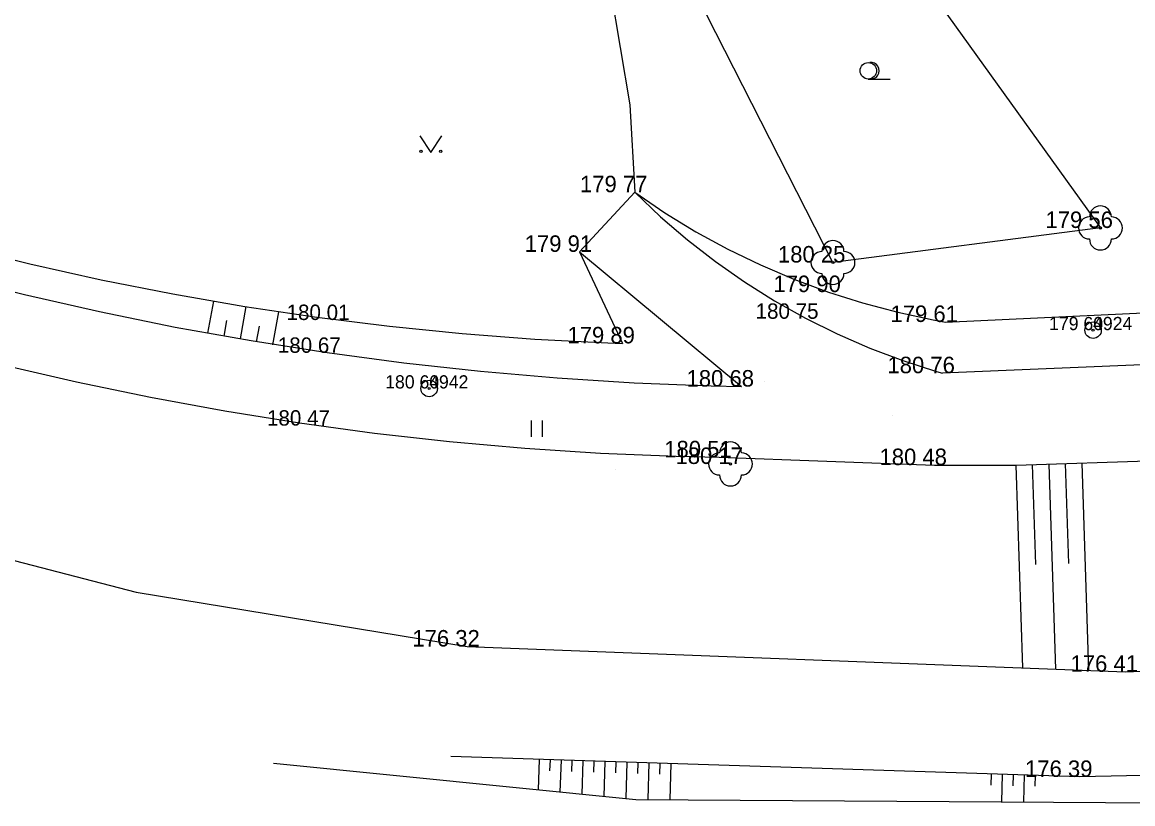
# Model space of a CAD drawing. Extents: x -537755 to -537431, y -1180722 to -1180510.
# Drawn here: x -537528.9 to -537478.3, y -1180722.3 to -1180686.8 of the extents above; entities that cross this region are included whole.
import ezdxf

# ---------------------------------------------------------------- set-up
doc = ezdxf.new("R2010")
doc.units = 0
for name, color, linetype in [('Vrstva 1', 7, 'Continuous'), ('Vrstva 10', 7, 'Continuous'), ('Vrstva 11', 7, 'Continuous'), ('Vrstva 14', 7, 'Continuous'), ('Vrstva 15', 7, 'Continuous'), ('Vrstva 21', 7, 'Continuous'), ('Vrstva 22', 7, 'Continuous'), ('Vrstva 23', 7, 'Continuous'), ('Vrstva 3', 7, 'Continuous'), ('Vrstva 36', 7, 'Continuous')]:
    doc.layers.add(name, color=color, linetype=linetype)

msp = doc.modelspace()

# ---------------------------------------------------------------- linework, layer by layer
at = {"layer": 'Vrstva 1'}
for p, q in [((-537500.986, -1180694.536), (-537500.986, -1180694.536)), ((-537479.81, -1180696.16), (-537479.81, -1180696.16)), ((-537503.5, -1180697.246), (-537503.5, -1180697.246)), ((-537491.98, -1180697.73), (-537491.98, -1180697.73)), ((-537492.186, -1180699.075), (-537492.186, -1180699.075)), ((-537514.499, -1180700.344), (-537514.499, -1180700.344)), ((-537493.164, -1180700.289), (-537493.164, -1180700.289)), ((-537486.861, -1180700.435), (-537486.861, -1180700.435)), ((-537501.555, -1180701.407), (-537501.555, -1180701.407)), ((-537514.898, -1180701.836), (-537514.898, -1180701.836)), ((-537486.999, -1180702.764), (-537486.999, -1180702.764)), ((-537496.137, -1180703.371), (-537496.137, -1180703.371)), ((-537495.07, -1180703.14), (-537495.07, -1180703.14)), ((-537489.28, -1180704.69), (-537489.28, -1180704.69)), ((-537515.39, -1180705.145), (-537515.39, -1180705.145)), ((-537497.151, -1180706.588), (-537497.151, -1180706.588)), ((-537496.64, -1180706.89), (-537496.64, -1180706.89)), ((-537487.36, -1180706.941), (-537487.36, -1180706.941)), ((-537501.85, -1180707.16), (-537501.85, -1180707.16)), ((-537508.61, -1180715.19), (-537508.61, -1180715.19)), ((-537478.67, -1180716.34), (-537478.67, -1180716.34)), ((-537480.74, -1180721.12), (-537480.74, -1180721.12))]:
    msp.add_line(p, q, dxfattribs=at)
at = {"layer": 'Vrstva 10'}
for points in [[(-537502.97, -1180680.12), (-537501.22, -1180690.564)], [(-537501.22, -1180690.564), (-537500.986, -1180694.536)]]:
    msp.add_lwpolyline(points, dxfattribs=at)
at = {"layer": 'Vrstva 11'}
msp.add_line((-537503.5, -1180697.246), (-537500.986, -1180694.536), dxfattribs=at)
at = {"layer": 'Vrstva 14'}
for p, q in [((-537503.5, -1180697.246), (-537501.555, -1180701.407)), ((-537503.5, -1180697.246), (-537496.137, -1180703.371)), ((-537486.861, -1180700.435), (-537466.378, -1180699.474)), ((-537512.155, -1180700.628), (-537508.849, -1180700.959)), ((-537518.448, -1180701.283), (-537514.981, -1180701.824)), ((-537466.466, -1180701.894), (-537486.999, -1180702.764)), ((-537508.015, -1180702.668), (-537504.52, -1180702.971)), ((-537519.642, -1180704.479), (-537516.245, -1180705.021)), ((-537509.416, -1180705.868), (-537505.989, -1180706.172)), ((-537483.645, -1180706.944), (-537466.003, -1180706.367)), ((-537497.151, -1180706.588), (-537487.36, -1180706.941)), ((-537487.36, -1180706.941), (-537483.645, -1180706.944)), ((-537544.01, -1180707.46), (-537523.671, -1180712.712)), ((-537523.671, -1180712.712), (-537508.61, -1180715.19)), ((-537478.67, -1180716.34), (-537431.26, -1180714.51)), ((-537508.61, -1180715.19), (-537478.67, -1180716.34)), ((-537480.74, -1180721.12), (-537509.36, -1180720.19)), ((-537432.66, -1180719.92), (-537480.74, -1180721.12)), ((-537517.43, -1180720.49), (-537500.95, -1180722.15)), ((-537500.95, -1180722.15), (-537468.69, -1180722.34))]:
    msp.add_line(p, q, dxfattribs=at)
for points in [[(-537500.986, -1180694.536), (-537499.62, -1180695.466), (-537498.211, -1180696.328), (-537496.761, -1180697.121), (-537495.275, -1180697.843), (-537493.755, -1180698.493), (-537492.186, -1180699.075)], [(-537500.986, -1180694.536), (-537499.817, -1180695.646), (-537498.594, -1180696.696), (-537497.32, -1180697.685), (-537495.999, -1180698.609), (-537494.634, -1180699.466), (-537493.228, -1180700.255)], [(-537531.733, -1180696.981), (-537528.51, -1180697.785), (-537525.268, -1180698.511), (-537522.01, -1180699.158)], [(-537532.164, -1180698.334), (-537528.761, -1180699.188), (-537525.339, -1180699.965)], [(-537522.01, -1180699.158), (-537518.737, -1180699.727), (-537515.451, -1180700.217), (-537512.155, -1180700.628)], [(-537492.186, -1180699.075), (-537490.631, -1180699.567), (-537489.034, -1180699.99), (-537487.418, -1180700.335), (-537486.861, -1180700.435)], [(-537525.339, -1180699.965), (-537521.901, -1180700.663), (-537518.448, -1180701.283)], [(-537493.228, -1180700.255), (-537491.785, -1180700.973), (-537490.307, -1180701.619), (-537488.8, -1180702.19), (-537487.266, -1180702.686), (-537486.999, -1180702.764)], [(-537508.849, -1180700.959), (-537505.537, -1180701.211), (-537502.219, -1180701.382), (-537501.555, -1180701.407)], [(-537533.08, -1180701.525), (-537529.747, -1180702.38), (-537526.396, -1180703.158)], [(-537514.981, -1180701.824), (-537511.503, -1180702.286), (-537508.015, -1180702.668)], [(-537504.52, -1180702.971), (-537501.018, -1180703.194), (-537497.512, -1180703.337), (-537496.137, -1180703.371)], [(-537526.396, -1180703.158), (-537523.027, -1180703.858), (-537519.642, -1180704.479)], [(-537516.245, -1180705.021), (-537512.835, -1180705.484), (-537509.416, -1180705.868)], [(-537505.989, -1180706.172), (-537502.555, -1180706.397), (-537499.117, -1180706.541), (-537497.151, -1180706.588)]]:
    msp.add_lwpolyline(points, dxfattribs=at)
at = {"layer": 'Vrstva 15'}
for p, q in [((-537520.163, -1180699.489), (-537520.426, -1180700.938)), ((-537518.683, -1180699.736), (-537518.95, -1180701.205)), ((-537517.201, -1180699.966), (-537517.474, -1180701.473)), ((-537519.56, -1180700.365), (-537519.688, -1180701.072)), ((-537518.084, -1180700.632), (-537518.212, -1180701.339)), ((-537483.343, -1180716.16), (-537483.645, -1180706.944)), ((-537482.746, -1180711.464), (-537482.895, -1180706.92)), ((-537481.841, -1180716.218), (-537482.145, -1180706.895)), ((-537481.247, -1180711.415), (-537481.396, -1180706.871)), ((-537480.337, -1180716.276), (-537480.646, -1180706.846)), ((-537505.348, -1180720.32), (-537505.392, -1180721.703)), ((-537504.848, -1180720.337), (-537504.865, -1180720.836)), ((-537504.349, -1180720.353), (-537504.395, -1180721.803)), ((-537503.849, -1180720.369), (-537503.865, -1180720.869)), ((-537503.349, -1180720.385), (-537503.399, -1180721.903)), ((-537502.849, -1180720.402), (-537502.866, -1180720.901)), ((-537502.35, -1180720.418), (-537502.401, -1180722.004)), ((-537501.85, -1180720.434), (-537501.866, -1180720.934)), ((-537501.35, -1180720.45), (-537501.405, -1180722.104)), ((-537500.85, -1180720.467), (-537500.867, -1180720.966)), ((-537500.351, -1180720.483), (-537500.405, -1180722.153)), ((-537499.851, -1180720.499), (-537499.867, -1180720.999)), ((-537499.351, -1180720.515), (-537499.405, -1180722.159)), ((-537484.781, -1180720.989), (-537484.791, -1180721.499)), ((-537484.281, -1180721.005), (-537484.306, -1180722.248)), ((-537483.781, -1180721.021), (-537483.791, -1180721.519)), ((-537483.281, -1180721.037), (-537483.305, -1180722.254)), ((-537482.781, -1180721.054), (-537482.791, -1180721.539))]:
    msp.add_line(p, q, dxfattribs=at)
at = {"layer": 'Vrstva 21'}
for centre, radius in [((-537480.145, -1180700.805), 0.375), ((-537480.145, -1180700.805), 0.05), ((-537510.347, -1180703.457), 0.375), ((-537510.347, -1180703.457), 0.05)]:
    msp.add_circle(centre, radius, dxfattribs=at)
at = {"layer": 'Vrstva 22'}
for centre in [(-537479.81, -1180696.16), (-537491.98, -1180697.73), (-537496.64, -1180706.89)]:
    msp.add_circle(centre, 0.05, dxfattribs=at)
for centre, start, end in [((-537479.81, -1180695.66), 0, 180), ((-537480.31, -1180696.16), 90, 270), ((-537479.31, -1180696.16), 270, 90), ((-537491.98, -1180697.23), 0, 180), ((-537479.81, -1180696.66), 180, 0), ((-537492.48, -1180697.73), 90, 270), ((-537491.48, -1180697.73), 270, 90), ((-537491.98, -1180698.23), 180, 0), ((-537496.64, -1180706.39), 0, 180), ((-537497.14, -1180706.89), 90, 270), ((-537496.14, -1180706.89), 270, 90), ((-537496.64, -1180707.39), 180, 0)]:
    msp.add_arc(centre, 0.5, start, end, dxfattribs=at)
at = {"layer": 'Vrstva 23'}
for p, q in [((-537493.21, -1180677.51), (-537479.81, -1180696.16)), ((-537491.98, -1180697.73), (-537498.92, -1180684.12)), ((-537479.81, -1180696.16), (-537491.98, -1180697.73))]:
    msp.add_line(p, q, dxfattribs=at)
at = {"layer": 'Vrstva 36'}
for p, q in [((-537490.369, -1180689.387), (-537489.369, -1180689.387)), ((-537505.688, -1180705.661), (-537505.688, -1180704.911)), ((-537505.188, -1180705.661), (-537505.188, -1180704.911))]:
    msp.add_line(p, q, dxfattribs=at)
msp.add_lwpolyline([(-537510.768, -1180691.975), (-537510.268, -1180692.725), (-537509.768, -1180691.975)], dxfattribs=at)
for centre, radius in [((-537490.369, -1180689.012), 0.375), ((-537510.718, -1180692.675), 0.05), ((-537509.819, -1180692.675), 0.05)]:
    msp.add_circle(centre, radius, dxfattribs=at)
msp.add_arc((-537490.244, -1180689.012), 0.375, 260.4059, 99.5941, dxfattribs=at)

# ---------------------------------------------------------------- texts
at = {"layer": 'Vrstva 22'}
for s, p in [('179 60 ', (-537482.145, -1180700.805)), ('180 60 ', (-537512.347, -1180703.457))]:
    msp.add_text(s, height=0.6, dxfattribs=at).set_placement(p)
at = {"layer": 'Vrstva 23'}
for s, p in [('4924', (-537480.145, -1180700.805)), ('4942', (-537510.347, -1180703.457))]:
    msp.add_text(s, height=0.6, dxfattribs=at).set_placement(p)
at = {"layer": 'Vrstva 3'}
for s, height, p in [('179 77 ', 0.75, (-537503.486, -1180694.536)), ('179 56 ', 0.75, (-537482.31, -1180696.16)), ('179 91 ', 0.75, (-537506, -1180697.246)), ('180 25 ', 0.75, (-537494.48, -1180697.73)), ('179 90 ', 0.75, (-537494.686, -1180699.075)), ('180 01 ', 0.7, (-537516.832, -1180700.344)), ('180 75 ', 0.7, (-537495.497, -1180700.289)), ('179 61 ', 0.75, (-537489.361, -1180700.435)), ('179 89 ', 0.75, (-537504.055, -1180701.407)), ('180 67 ', 0.7, (-537517.231, -1180701.836)), ('180 76 ', 0.75, (-537489.499, -1180702.764)), ('180 68 ', 0.75, (-537498.637, -1180703.371)), ('180 47 ', 0.7, (-537517.723, -1180705.145)), ('180 51 ', 0.75, (-537499.651, -1180706.588)), ('180 17 ', 0.75, (-537499.14, -1180706.89)), ('180 48 ', 0.75, (-537489.86, -1180706.941)), ('176 32 ', 0.75, (-537511.11, -1180715.19)), ('176 41 ', 0.75, (-537481.17, -1180716.34)), ('176 39 ', 0.75, (-537483.24, -1180721.12))]:
    msp.add_text(s, height=height, dxfattribs=at).set_placement(p)

doc.saveas('drawing.dxf')
